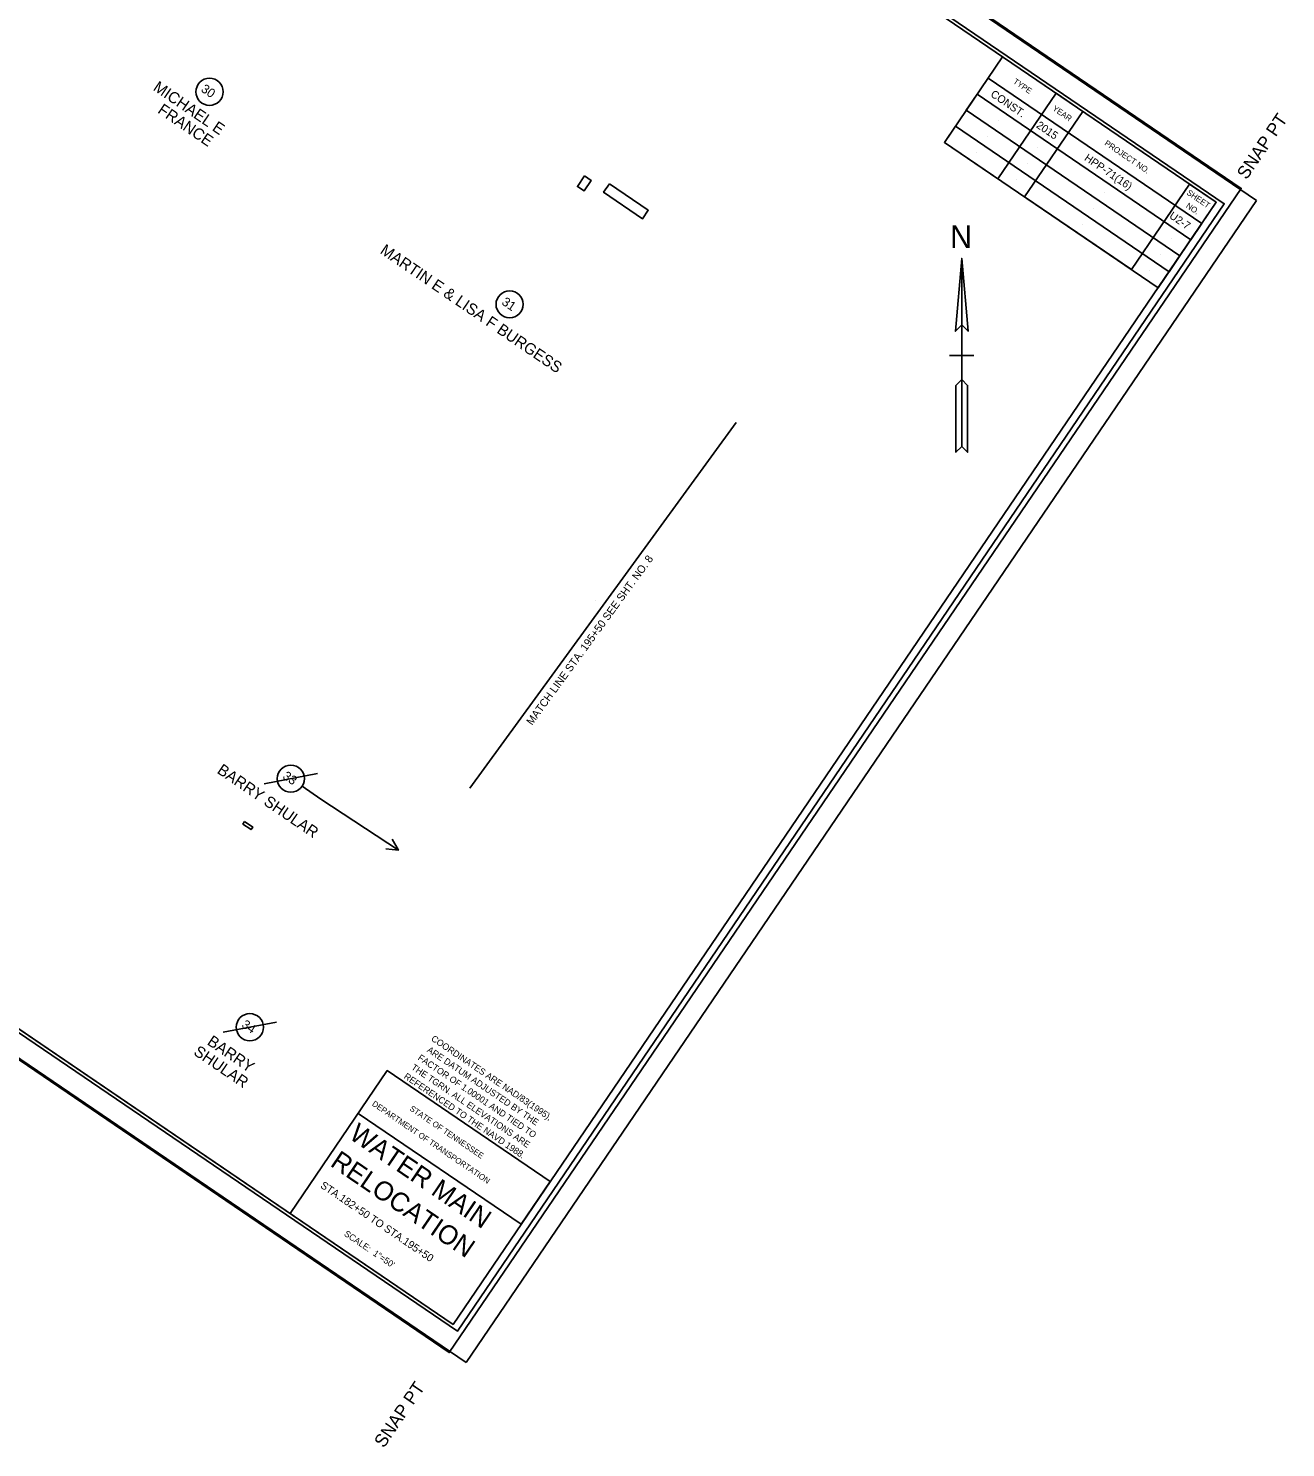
# Model space of a CAD drawing. Extents: x 2629906 to 2632029, y 567681 to 569670.
# Drawn here: x 2631056 to 2632029, y 567681 to 568779 of the extents above; entities that cross this region are included whole.
import ezdxf

# ---------------------------------------------------------------- set-up
doc = ezdxf.new("R2010")
doc.units = 0
for name, color, linetype in [('DESIGN - CENTERLINE - Proposed Text', 7, 'Continuous'), ('DESIGN - SCRATCH - User 1', 7, 'Continuous'), ('DESIGN - SHEET - Corner Text', 7, 'Continuous'), ('DESIGN - SHEET - Light Grid', 7, 'Continuous'), ('DESIGN - SHEET - Linework', 7, 'Continuous'), ('DESIGN - SHEET - Plot Shape', 7, 'Continuous'), ('SURVEY - PROPERTY - Owners', 7, 'Continuous'), ('SURVEY - PROPERTY - Tract Numbers', 7, 'Continuous')]:
    doc.layers.add(name, color=color, linetype=linetype)

msp = doc.modelspace()

# ---------------------------------------------------------------- linework, layer by layer
at = {"layer": 'DESIGN - CENTERLINE - Proposed Text'}
for p, q in [((2631778.1, 568525.9), (2631768.7, 568525.9)), ((2631787.6, 568525.9), (2631778.1, 568525.9))]:
    msp.add_line(p, q, dxfattribs=at)
for points in [[(2631778.1, 568600.9), (2631773.2, 568544.6), (2631778.1, 568549.5), (2631783, 568544.6), (2631778.1, 568600.9), (2631778.1, 568455.4), (2631782.7, 568450.9), (2631782.7, 568502.6), (2631778.1, 568507.2), (2631773.6, 568502.6), (2631773.6, 568450.9), (2631778.1, 568455.4)], [(2631397.5, 568191.1), (2631500.6, 568332.6), (2631603.6, 568474)]]:
    msp.add_lwpolyline(points, dxfattribs=at)
for points in [[(2631778.1, 568549.5), (2631783, 568544.6), (2631778.1, 568600.9)], [(2631773.6, 568450.9), (2631778.1, 568455.4), (2631778.1, 568507.2), (2631773.6, 568502.6)]]:
    msp.add_lwpolyline(points, close=True, dxfattribs=at)
at = {"layer": 'DESIGN - SCRATCH - User 1'}
for p, q in [((2631815, 568720.1), (2631815, 568720.1)), ((2631806.5, 568707.7), (2631806.5, 568707.7)), ((2631845.6, 568699.2), (2631845.6, 568699.2)), ((2631798.1, 568695.2), (2631798.1, 568695.2)), ((2631837.1, 568686.8), (2631837.1, 568686.8)), ((2631789.7, 568682.8), (2631789.7, 568682.8)), ((2631828.7, 568674.4), (2631828.7, 568674.4)), ((2631897.2, 568664.1), (2631897.2, 568664.1)), ((2631820.3, 568662), (2631820.3, 568662)), ((2631888.8, 568651.7), (2631888.8, 568651.7)), ((2631880.4, 568639.3), (2631880.4, 568639.3)), ((2631871.9, 568626.9), (2631871.9, 568626.9)), ((2631948.9, 568628.9), (2631948.9, 568628.9)), ((2631940.5, 568616.5), (2631940.5, 568616.5)), ((2631932, 568604.1), (2631932, 568604.1)), ((2631923.6, 568591.7), (2631923.6, 568591.7)), ((2631494.5, 568336.4), (2631494.5, 568336.4)), ((2631347.8, 567857.8), (2631347.8, 567857.8))]:
    msp.add_line(p, q, dxfattribs=at)
at = {"layer": 'DESIGN - SHEET - Corner Text'}
for points in [[(2631486.3, 568664.7), (2631491.4, 568661.2), (2631485.9, 568653.1), (2631480.8, 568656.5)], [(2631505.5, 568658.7), (2631535.6, 568638.2), (2631531.2, 568631.6), (2631501, 568652.1)], [(2631223.2, 568165.2), (2631229.5, 568160.9), (2631228.3, 568159), (2631221.9, 568163.3)]]:
    msp.add_lwpolyline(points, close=True, dxfattribs=at)
at = {"layer": 'DESIGN - SHEET - Light Grid'}
msp.add_lwpolyline([(2630011.2, 568707.4), (2631387.9, 567770.9), (2631981.3, 568643.2), (2630604.6, 569579.7)], close=True, dxfattribs=at)
at = {"layer": 'DESIGN - SHEET - Linework'}
for p, q in [((2630518, 569658.2), (2632006.3, 568645.8)), ((2629906.4, 568759.1), (2631394.7, 567746.7)), ((2632006.3, 568645.8), (2631394.7, 567746.7))]:
    msp.add_line(p, q, dxfattribs=at)
for points in [[(2630673.6, 569529.8), (2630083, 568661.6), (2631384.6, 567776.2), (2631975.1, 568644.4), (2630673.6, 569529.8)], [(2631809.8, 568756.9), (2631764.8, 568690.7), (2631930.1, 568578.2), (2631975.1, 568644.4), (2631954.5, 568658.4), (2631909.5, 568592.3), (2631826.8, 568648.5), (2631871.8, 568714.7), (2631851.1, 568728.7), (2631806.1, 568662.6), (2631764.8, 568690.7), (2631773.2, 568703.1), (2631938.6, 568590.6), (2631947, 568603), (2631781.6, 568715.5), (2631790.1, 568727.9), (2631955.5, 568615.4), (2631963.9, 568627.8), (2631798.5, 568740.3)], [(2631258.5, 567862), (2631333.6, 567972.5), (2631459.7, 567886.7), (2631437.2, 567853.6), (2631311.1, 567939.4)]]:
    msp.add_lwpolyline(points, dxfattribs=at)
at = {"layer": 'DESIGN - SHEET - Plot Shape'}
for points in [[(2630588.8, 569611.3), (2631994.4, 568655.1), (2631381.6, 567754.4), (2629976, 568710.6)], [(2630603.2, 569577.6), (2631975.1, 568644.4), (2631384.6, 567776.2), (2630012.6, 568709.5)]]:
    msp.add_lwpolyline(points, close=True, dxfattribs=at)
at = {"layer": 'SURVEY - PROPERTY - Tract Numbers'}
for p, q in [((2631238.4, 568194.5), (2631279.6, 568202.3)), ((2631206.6, 568002.2), (2631247.9, 568010.1))]:
    msp.add_line(p, q, dxfattribs=at)
for points in [[(2631282.2, 568182.6), (2631267.7, 568192.5)], [(2631342.3, 568143.1), (2631282.2, 568182.6)], [(2631337.4, 568151.5), (2631342.3, 568143.1), (2631332.6, 568144.2)]]:
    msp.add_lwpolyline(points, dxfattribs=at)
for centre in [(2631196.1, 568729.8), (2631428.3, 568565.4), (2631259, 568198.4), (2631227.3, 568006.1)]:
    msp.add_circle(centre, 10.5, dxfattribs=at)

# ---------------------------------------------------------------- texts
at = {"layer": 'DESIGN - CENTERLINE - Proposed Text'}
msp.add_text('N', height=17.7, dxfattribs=at).set_placement((2631769.1, 568608.9))
msp.add_text('MATCH LINE STA. 195+50 SEE SHT. NO. 8', height=6, rotation=53.918, dxfattribs=at).set_placement((2631445.6, 568239.3))
at = {"layer": 'DESIGN - SHEET - Corner Text'}
for s, height, rotation, p in [('TYPE', 4.5, 325.7738, (2631817.5, 568736.8)), ('CONST.', 6, 325.7738, (2631799.9, 568726.7)), ('YEAR', 4.5, 325.7738, (2631847.9, 568715.9)), ('  SNAP PT', 10, 55.7738, (2631994.4, 568655.1)), ('2015', 6, 325.7738, (2631835.3, 568702.6)), ('PROJECT NO.', 4.5, 325.7738, (2631888.2, 568689)), ('HPP-71(16)', 6, 325.7738, (2631872.5, 568677.3)), ('SHEET', 4.5, 325.7738, (2631951.8, 568650.7)), ('NO.', 4.5, 325.7738, (2631951.2, 568640.6)), ('U2-7', 6, 325.7738, (2631938.2, 568632.6)), ('COORDINATES ARE NAD/83(1995),', 5, 325.7738, (2631367.1, 567996.1)), ('FACTOR OF 1.00001 AND TIED TO', 5, 325.7738, (2631356.8, 567981.3)), ('ARE DATUM ADJUSTED BY THE', 5, 325.7738, (2631363.9, 567987.4)), ('THE TGRN. ALL ELEVATIONS ARE', 5, 325.7738, (2631351.7, 567973.9)), ('REFERENCED TO THE NAVD 1988.', 5, 325.7738, (2631346, 567966.9)), ('DEPARTMENT OF TRANSPORTATION', 4.5, 325.7738, (2631321.4, 567945.8)), ('STATE OF TENNESSEE', 4.5, 325.7738, (2631350.5, 567942.1)), ('WATER MAIN', 14.76, 325.7738, (2631303.2, 567920.5)), ('RELOCATION', 14.76, 325.7738, (2631288.7, 567899.2)), ('STA.182+50 TO STA.195+50', 5.905, 325.7738, (2631281.3, 567882.4)), ('SCALE:  1"=50\'', 4.921, 325.7738, (2631299.7, 567845.2)), ('SNAP PT  ', 10, 55.7738, (2631331, 567680))]:
    msp.add_text(s, height=height, rotation=rotation, dxfattribs=at).set_placement(p)
at = {"layer": 'SURVEY - PROPERTY - Owners'}
for s, p in [('MICHAEL E', (2631151.8, 568731.5)), ('FRANCE', (2631155.3, 568714)), ('MARTIN E & LISA F BURGESS', (2631327.4, 568605.3)), ('BARRY SHULAR', (2631201.3, 568203.2)), ('BARRY', (2631193.6, 567993.2)), ('SHULAR', (2631183.1, 567985.3))]:
    msp.add_text(s, height=8.75, rotation=325.7738, dxfattribs=at).set_placement(p)
at = {"layer": 'SURVEY - PROPERTY - Tract Numbers'}
for s, p in [('30', (2631188.9, 568730.5)), ('31', (2631421.6, 568565.7)), ('33', (2631252.1, 568198.9)), ('34', (2631220.3, 568006.6))]:
    msp.add_text(s, height=7, rotation=325.7738, dxfattribs=at).set_placement(p)

doc.saveas('drawing.dxf')
